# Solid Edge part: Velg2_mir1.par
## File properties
Author: KULL
Template: Iso Metric Part.par
Last saved by: KULL
Revision: 2
Application: Solid Edge
Accuracy: 0,990
Username: KULL
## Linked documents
Velg2.par
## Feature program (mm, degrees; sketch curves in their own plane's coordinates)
part copy "CopiedPart_1"
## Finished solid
Body 1: solid body, 389 faces, 931 edges, 512 vertices.
  Faces by surface: blend 256, torus 63, swept 32, cylinder 24, cone 10, plane 2, spun 2
  Edges by curve: intersection 512, circle 403, line 16
Bounding box of the edges (mm; curved faces can reach further): 43.118 x 87.299 x 87.299, from (-41.1766, -43.6493, -43.6493) to (1.9413, 43.6493, 43.6493).
Cylindrical faces by radius (mm): R4 x1, R8 x1, R10 x1, R36.3826 x1, R38.3116 x17, R38.3826 x1, R40.3116 x2
Conical faces (half-angle, radius in mm at the cone's reference point): 14.1898 deg R43.1591 x1, 14.1898 deg R43.6493 x1, 17.3646 deg R36.5649 x1, 17.3646 deg R38.1293 x1, 17.3646 deg R38.5649 x1, 17.3646 deg R40.1293 x1, 75.8102 deg R41.0291 x1, 75.8102 deg R41.5194 x1, 75.8102 deg R43.1591 x1, 75.8102 deg R43.6493 x1
Toroidal faces (ring radius, tube radius in mm): R8.1 r0.1 x1, R13 r3 x1, R34.3116 r4 x17, R36.3116 r4 x2, R36.7771 r0.6 x16, R38.0022 r0.6 x16, R40.3826 r4 x2, R41.9116 r1.6 x2, R41.9116 r3.6 x2, R42.3826 r4 x2, R43.0142 r0.2 x2
Planar faces by outward normal: +x 1, -x 1
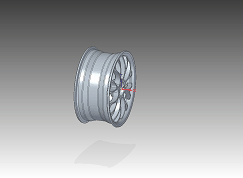
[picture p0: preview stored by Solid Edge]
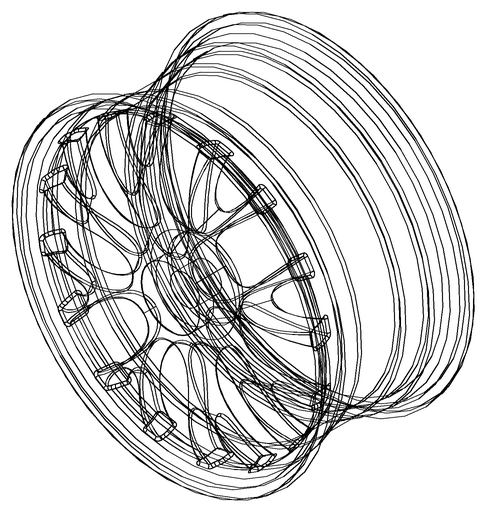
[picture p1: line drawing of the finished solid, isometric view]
